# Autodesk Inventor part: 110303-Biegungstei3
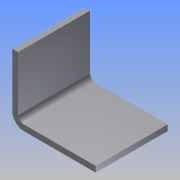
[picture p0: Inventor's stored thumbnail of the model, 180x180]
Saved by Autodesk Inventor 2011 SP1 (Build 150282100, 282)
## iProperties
Manager: Michael Puschner
Company: Mensch und Maschine Scholle GmbH
Created: 2011-03
Part Number: 110303-Biegungstei3
Document SubType Name: Blech
Designer: MP
Mass: 19.3717 g
Surface Area: 108.607 cm^2
Volume: 19.3717 cm^3
Density: 1 g/cm^3
Flat Pattern Width: 5 cm
Flat Pattern Length: 10 cm
Flat Pattern Area: 50 cm^2
Sheet Metal Rule: Standard
Sheet Metal Width: 50,000 mm
Sheet Metal Length: 100,000 mm
Sheet Metal Area: 5000,000 mm^2
Title: Norm.ipt
Author: MP
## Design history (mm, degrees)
sketch "Skizze1"
  geometry: L1 (-50, 25)-(50, 25); L2 (50, 25)-(50, -25); L3 (50, -25)-(-50, -25); L4 (-50, -25)-(-50, 25); L5 (0, 25)-(0, -25); 2 further points
  constraints: 10 end point, 3 midpoint, 2 parallel, 1 horizontal, 1 horizontal alignment, 1 perpendicular, 1 vertical alignment
  dimensions: "d0" = 100 distance of L1.start L1.end; "d1" = 50 distance of L3.end L1.start
extrude "Extrusion1" new body sketch "Skizze1" distance "d2" = 4; taper "d3" = 0 deg
feature "Biegungsteil1" dims "d4" = 8, "d5" = 90 deg
node "Volumenkörper1"
feature "Definition1"
other parameters: "Stärke" = 4 (derived), "KFaktor" = 4.4, "Biegeradius" = 4 (= Stärke), "BreiteBiegungsfreistellung" = 4 (= Stärke), "TiefeBiegungsfreistellung" = 2 (= 0.5 x Stärke), "GrößeEckenfreistellung" = 16 (= 4 x Stärke), "AbstandVerbindung" = 0.01, "MinimalRest" = 8 (= 2 x Stärke), "Übergangsradius" = 4 (= Biegeradius), "JacobiRadiusGröße" = 4 (= Biegeradius), "Abstandsgröße" = 4 (= Stärke), "Abstandsgröße" = 4, "Biegeradius" = 4, "BreiteBiegungsfreistellung" = 4, "GrößeEckenfreistellung" = 16, "JacobiRadiusGröße" = 4, "MinimalRest" = 8, "Stärke" = 4, "TiefeBiegungsfreistellung" = 2, "Übergangsradius" = 4
